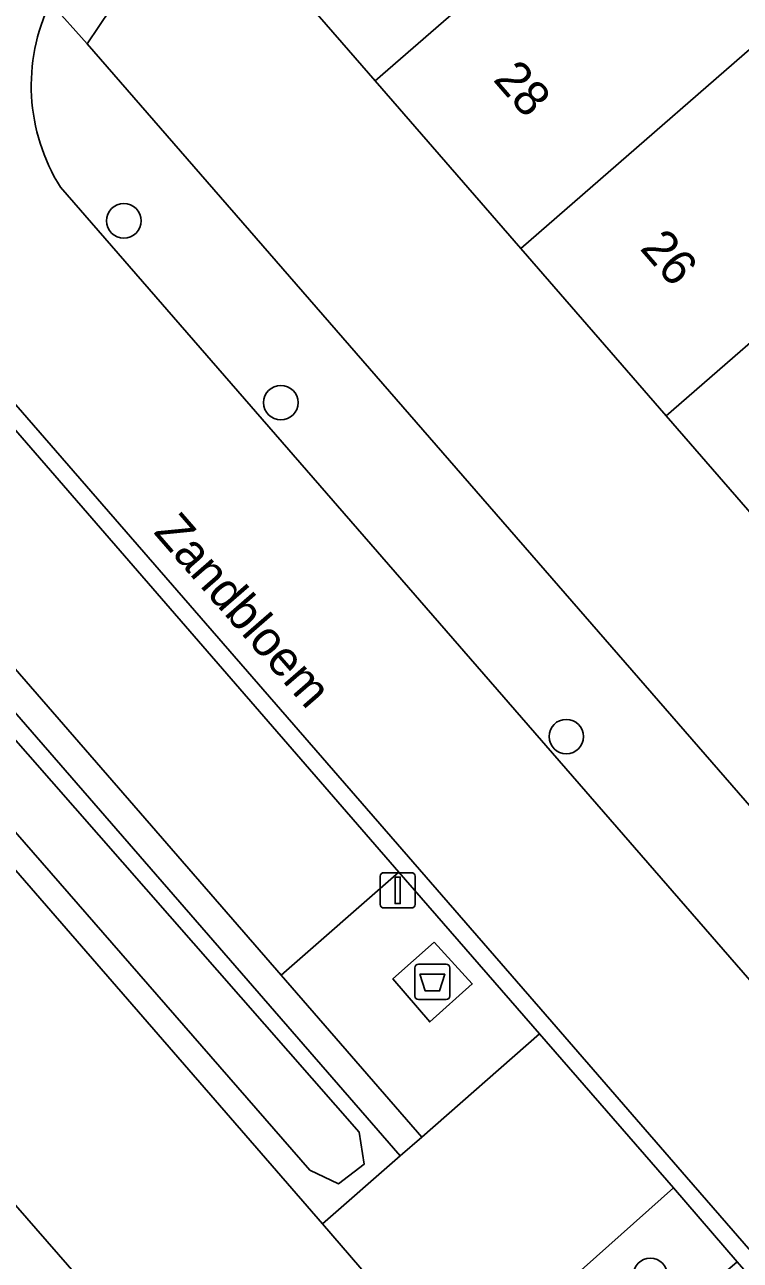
# Model space of a CAD drawing. Extents: x 155887 to 156869, y 383880 to 384678.
# Drawn here: x 156326.38 to 156346.67, y 384014.44 to 384049.47 of the extents above; entities that cross this region are included whole.
import ezdxf

# ---------------------------------------------------------------- set-up
doc = ezdxf.new("R2010")
doc.units = 0
for name, color, linetype in [('IMGEO_Afval_apart_plaats', 7, 'Continuous'), ('IMGEO_Berm_groen', 7, 'Continuous'), ('IMGEO_Boom', 7, 'Continuous'), ('IMGEO_Erf', 7, 'Continuous'), ('IMGEO_Greppel_droge_sloot', 7, 'Continuous'), ('IMGEO_Lichtmast', 7, 'Continuous'), ('IMGEO_Openbare_ruimte_label', 7, 'Continuous'), ('IMGEO_Pand', 7, 'Continuous'), ('IMGEO_Pand_nummerreeks', 7, 'Continuous'), ('IMGEO_Parkeervlak_open', 7, 'Continuous'), ('IMGEO_Rijbaan_lokaal_gesloten', 7, 'Continuous'), ('IMGEO_Rijbaan_lokaal_open', 7, 'Continuous'), ('IMGEO_Voetpad_gesloten', 7, 'Continuous'), ('IMGEO_Voetpad_open', 7, 'Continuous')]:
    doc.layers.add(name, color=color, linetype=linetype)

msp = doc.modelspace()

# ---------------------------------------------------------------- linework, layer by layer
at = {"layer": 'IMGEO_Afval_apart_plaats'}
for p, q in [((156337.444, 384021.934), (156337.444, 384022.734)), ((156337.444, 384022.734), (156337.444, 384021.934)), ((156337.544, 384022.834), (156338.334, 384022.834)), ((156338.334, 384022.834), (156337.544, 384022.834)), ((156338.434, 384022.734), (156338.434, 384021.934)), ((156338.434, 384021.934), (156338.434, 384022.734)), ((156338.334, 384021.834), (156337.544, 384021.834)), ((156337.544, 384021.834), (156338.334, 384021.834))]:
    msp.add_line(p, q, dxfattribs=at)
msp.add_lwpolyline([(156337.587, 384022.548), (156338.291, 384022.548), (156338.142, 384022.078), (156337.736, 384022.078), (156337.587, 384022.548)], dxfattribs=at)
for centre, start, end in [((156337.544, 384022.734), 90, 180), ((156337.544, 384022.734), 90, 180), ((156338.334, 384022.734), 0, 90), ((156338.334, 384022.734), 360, 90), ((156337.544, 384021.934), 180, 270), ((156337.544, 384021.934), 180, 270), ((156338.334, 384021.934), 270, 0), ((156338.334, 384021.934), 270, 0)]:
    msp.add_arc(centre, 0.1, start, end, dxfattribs=at)
at = {"layer": 'IMGEO_Berm_groen'}
for points in [[(156309.711, 384048.832), (156307.48, 384046.967), (156334.824, 384015.476), (156337.029, 384017.397)], [(156310.286, 384047.24), (156335.861, 384018.073), (156336.002, 384017.163), (156335.275, 384016.608), (156334.468, 384016.994), (156309.059, 384046.139)]]:
    msp.add_lwpolyline(points, close=True, dxfattribs=at)
at = {"layer": 'IMGEO_Boom'}
for centre in [(156329.19, 384043.912), (156333.642, 384038.757), (156341.738, 384029.288), (156344.121, 384014.011)]:
    msp.add_circle(centre, 0.489, dxfattribs=at)
at = {"layer": 'IMGEO_Erf'}
for points in [[(156372.634, 384088.199), (156329.142, 384050.413), (156328.149, 384048.934), (156360.938, 384011.241), (156362.61, 384011.694), (156406.195, 384049.568)], [(156374.189, 384022.144), (156365.338, 384014.487), (156361.085, 384019.381), (156356.957, 384024.132), (156352.823, 384028.89), (156348.703, 384033.632), (156344.574, 384038.383), (156340.448, 384043.132), (156336.32, 384047.883), (156332.03, 384052.82), (156340.861, 384060.488), (156342.001, 384061.483), (156347.913, 384066.639), (156348.044, 384066.488), (156342.126, 384061.327), (156340.992, 384060.338), (156345.147, 384055.557), (156349.27, 384050.813), (156353.399, 384046.062), (156357.534, 384041.306), (156361.657, 384036.563), (156365.79, 384031.808), (156369.924, 384027.051), (156374.058, 384022.295)], [(156330.352, 384011.144), (156323.669, 384018.8), (156322.461, 384020.185), (156319.842, 384023.185), (156323.025, 384025.975), (156311.909, 384038.787), (156309.249, 384036.526), (156317.037, 384027.543), (156316.55, 384027.123), (156316.047, 384027.689), (156310.859, 384025.144), (156315.763, 384019.518), (156316.948, 384018.159), (156326.192, 384007.554)]]:
    msp.add_lwpolyline(points, dxfattribs=at)
at = {"layer": 'IMGEO_Greppel_droge_sloot'}
msp.add_lwpolyline([(156335.275, 384016.608), (156336.002, 384017.163), (156335.861, 384018.073), (156310.286, 384047.24), (156309.059, 384046.139), (156334.468, 384016.994)], close=True, dxfattribs=at)
at = {"layer": 'IMGEO_Lichtmast'}
for p, q in [((156336.461, 384024.529), (156336.461, 384025.329)), ((156336.461, 384025.329), (156336.461, 384024.529)), ((156336.561, 384025.429), (156337.351, 384025.429)), ((156337.351, 384025.429), (156336.561, 384025.429)), ((156337.451, 384025.329), (156337.451, 384024.529)), ((156337.451, 384024.529), (156337.451, 384025.329)), ((156337.351, 384024.429), (156336.561, 384024.429)), ((156336.561, 384024.429), (156337.351, 384024.429))]:
    msp.add_line(p, q, dxfattribs=at)
msp.add_lwpolyline([(156336.881, 384025.304), (156337.031, 384025.304), (156337.031, 384024.554), (156336.881, 384024.554), (156336.881, 384025.304)], dxfattribs=at)
for centre, start, end in [((156336.561, 384025.329), 90, 180), ((156336.561, 384025.329), 90, 180), ((156337.351, 384025.329), 0, 90), ((156337.351, 384025.329), 360, 90), ((156336.561, 384024.529), 180, 270), ((156336.561, 384024.529), 180, 270), ((156337.351, 384024.529), 270, 0), ((156337.351, 384024.529), 270, 0)]:
    msp.add_arc(centre, 0.1, start, end, dxfattribs=at)
at = {"layer": 'IMGEO_Pand'}
for points in [[(156336.32, 384047.883), (156345.147, 384055.557), (156340.992, 384060.338), (156340.861, 384060.488), (156332.03, 384052.82)], [(156340.448, 384043.132), (156349.27, 384050.813), (156345.147, 384055.557), (156336.32, 384047.883)], [(156340.448, 384043.132), (156344.574, 384038.383), (156353.399, 384046.062), (156349.27, 384050.813)], [(156353.399, 384046.062), (156344.574, 384038.383), (156348.703, 384033.632), (156357.534, 384041.306)]]:
    msp.add_lwpolyline(points, close=True, dxfattribs=at)
at = {"layer": 'IMGEO_Parkeervlak_open'}
msp.add_lwpolyline([(156333.649, 384022.524), (156336.989, 384025.442), (156314.932, 384050.866), (156313.707, 384052.278), (156310.33, 384049.351), (156311.573, 384047.941)], close=True, dxfattribs=at)
at = {"layer": 'IMGEO_Rijbaan_lokaal_gesloten'}
for points in [[(156317.543, 384056.292), (156284.205, 384094.584), (156280.427, 384091.296), (156283.957, 384087.246), (156289.413, 384080.986), (156306.544, 384061.236), (156310.724, 384056.416), (156314.044, 384052.599), (156341.332, 384021.196), (156345.148, 384016.792), (156359.753, 384000), (156367.328, 383991.29), (156368.7, 383989.651), (156369.329, 383988.906)], [(156357.31, 384010.459), (156327.395, 384044.864)]]:
    msp.add_lwpolyline(points, dxfattribs=at)
msp.add_arc((156331.969, 384047.742), 5.405, 154.1621, 212.1806, dxfattribs=at)
at = {"layer": 'IMGEO_Rijbaan_lokaal_open'}
for points in [[(156369.329, 383988.906), (156368.7, 383989.651), (156367.328, 383991.29), (156359.753, 384000), (156345.148, 384016.792), (156341.332, 384021.196), (156314.044, 384052.599), (156310.724, 384056.416), (156306.544, 384061.236), (156289.413, 384080.986), (156283.957, 384087.246), (156280.427, 384091.296)], [(156314.932, 384050.866), (156336.989, 384025.442), (156340.981, 384020.864), (156344.782, 384016.494), (156346.581, 384014.392), (156359.103, 384000), (156366.988, 383990.936), (156368.653, 383988.993), (156370.638, 383985.31), (156370.971, 383981.24), (156370.774, 383978.58), (156370.21, 383974.71), (156369.109, 383968.301), (156369.65, 383968.197), (156369.714, 383968.454), (156371.022, 383976.866), (156371.213, 383978.127), (156371.346, 383979.396), (156371.421, 383980.669), (156371.437, 383981.945)]]:
    msp.add_lwpolyline(points, dxfattribs=at)
at = {"layer": 'IMGEO_Voetpad_gesloten'}
msp.add_lwpolyline([(156337.989, 384023.46), (156336.821, 384022.416), (156337.865, 384021.198), (156339.069, 384022.276)], close=True, dxfattribs=at)
at = {"layer": 'IMGEO_Voetpad_open'}
for points in [[(156413.498, 384123.756), (156412.191, 384125.253), (156412.184, 384125.247), (156331.018, 384054.386), (156327.105, 384050.098), (156328.149, 384048.934), (156329.142, 384050.413), (156372.634, 384088.199), (156374.302, 384089.648), (156376.563, 384091.626)], [(156333.649, 384022.524), (156311.573, 384047.941), (156310.33, 384049.351), (156309.711, 384048.832), (156337.029, 384017.397), (156337.644, 384017.927)], [(156336.989, 384025.442), (156333.649, 384022.524), (156337.644, 384017.927), (156340.981, 384020.864)], [(156337.989, 384023.46), (156339.069, 384022.276), (156337.865, 384021.198), (156336.821, 384022.416)], [(156344.782, 384016.494), (156340.981, 384020.864), (156337.644, 384017.927), (156337.029, 384017.397), (156334.824, 384015.476), (156338.584, 384011.11), (156340.837, 384013.002), (156341.463, 384013.537)], [(156346.581, 384014.392), (156344.782, 384016.494), (156341.463, 384013.537), (156343.21, 384011.498)]]:
    msp.add_lwpolyline(points, close=True, dxfattribs=at)
for points in [[(156338.584, 384011.11), (156334.824, 384015.476), (156307.48, 384046.967), (156304.211, 384050.794)], [(156328.149, 384048.934), (156327.105, 384050.098)], [(156362.105, 384009.899), (156360.938, 384011.241), (156328.149, 384048.934)], [(156327.395, 384044.864), (156357.31, 384010.459)], [(156308.666, 384037.183), (156309.249, 384036.526), (156311.909, 384038.787), (156323.025, 384025.975), (156319.842, 384023.185), (156322.461, 384020.185), (156323.669, 384018.8), (156330.352, 384011.144), (156330.873, 384011.616), (156333.288, 384008.808), (156332.566, 384008.153), (156333.911, 384006.968), (156334.477, 384007.458), (156339.641, 384001.494), (156340.462, 384000.551), (156343.131, 384002.825), (156345.583, 384000), (156367.63, 383974.604)]]:
    msp.add_lwpolyline(points, dxfattribs=at)
msp.add_arc((156331.969, 384047.742), 5.405, 154.1621, 212.1806, dxfattribs=at)

# ---------------------------------------------------------------- texts
at = {"layer": 'IMGEO_Openbare_ruimte_label'}
msp.add_text('Zandbloem', height=1, rotation=310.9865, dxfattribs=at).set_placement((156330.012, 384035.075))
at = {"layer": 'IMGEO_Pand_nummerreeks'}
for s, p in [('28', (156339.638, 384047.908)), ('26', (156343.8, 384043.118))]:
    msp.add_text(s, height=1, rotation=310.9878, dxfattribs=at).set_placement(p)

doc.saveas('drawing.dxf')
